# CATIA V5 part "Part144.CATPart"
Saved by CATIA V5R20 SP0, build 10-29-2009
Part number: FA 084700-2 comprimido
Revision: ANY
Definition: UNKNOWN
Nomenclature: FA 084700-2 comprimido
Source: Unknown
Bounding box of the stored display mesh (mm): x -2.45 to 2.45, y 0 to 4.72, z -2.45 to 2.45
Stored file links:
  C:\Users\Utente\Desktop\IO LAVORO\3D X SITO CF\CUMSA\3D files FA\FA 105700\Part144.CATPart

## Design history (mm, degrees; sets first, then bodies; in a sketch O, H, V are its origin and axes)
Body1 "Cortar-Extruir1" (main body)
  Solid1: solid without history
